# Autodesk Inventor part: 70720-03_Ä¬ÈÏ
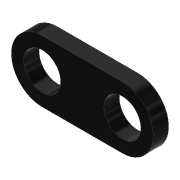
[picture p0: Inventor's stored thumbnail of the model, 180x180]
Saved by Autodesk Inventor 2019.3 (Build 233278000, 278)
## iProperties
Created: 2017-10
Part Number: 70720-03_Ä¬ÈÏ
Material: Ogólny
Document SubType Name: Modeling
Designer: CADENGINEERING4
Density: 1 g/cm^3
Appearance: Gładki — czarny
Author: CADENGINEERING4
Revision Number: ÈÎºÎ
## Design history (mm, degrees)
feature "ÊäÈë1"
node "Bryła1"
